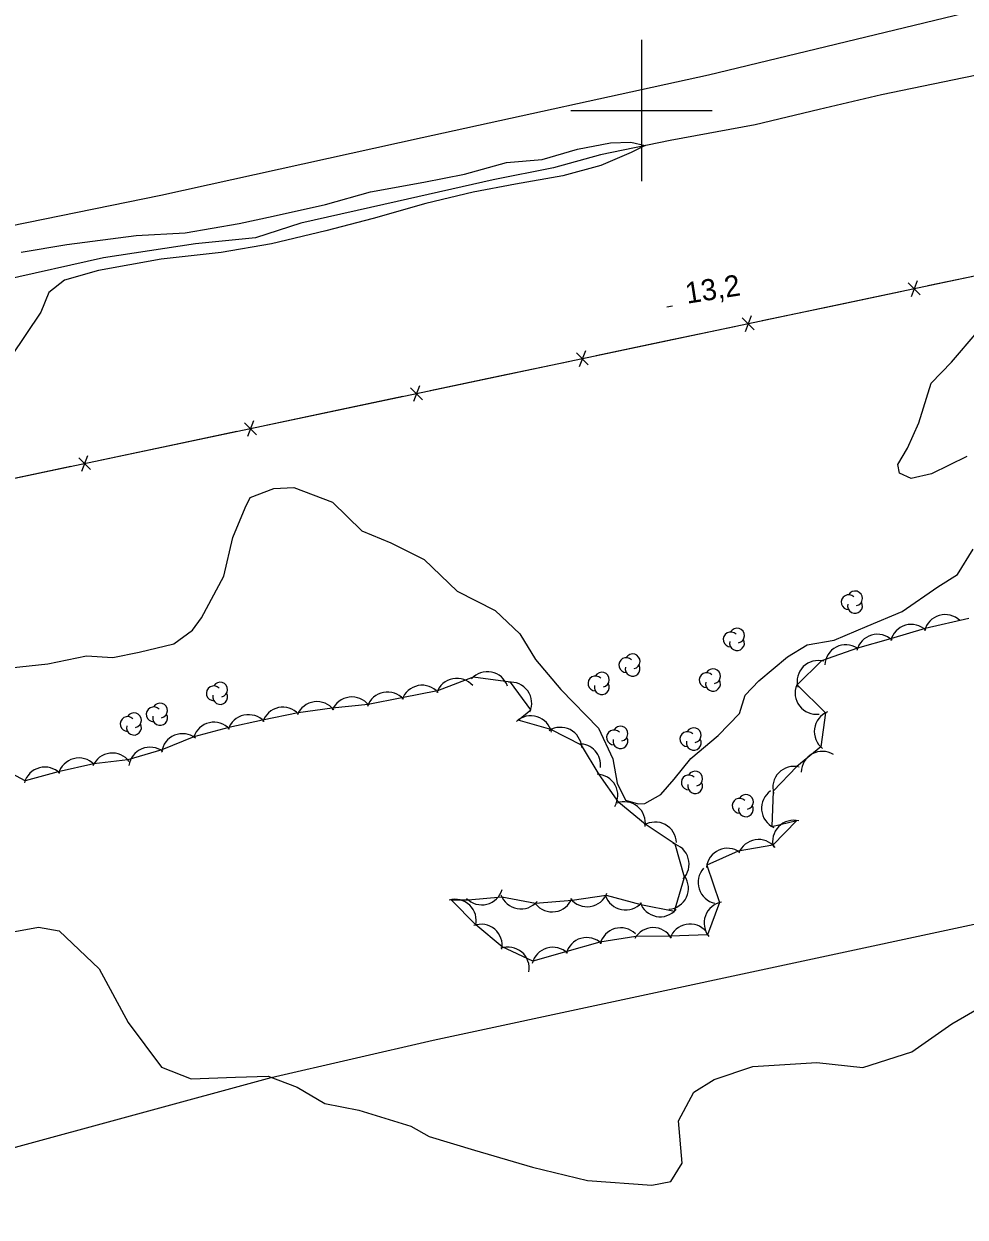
# Model space of a CAD drawing. Extents: x 643342 to 646936, y 5873857 to 5876103.
# Drawn here: x 645312.6 to 645445.8, y 5875443.4 to 5875612.3 of the extents above; entities that cross this region are included whole.
import ezdxf

# ---------------------------------------------------------------- set-up
doc = ezdxf.new("R2010")
doc.units = 0
for name, color, linetype in [('Niveau 1', 7, 'Continuous'), ('Niveau 2', 7, 'Continuous'), ('Niveau 25', 7, 'Continuous'), ('Niveau 3', 7, 'Continuous'), ('Niveau 37', 7, 'Continuous'), ('Niveau 4', 7, 'Continuous'), ('Niveau 44', 7, 'Continuous'), ('Niveau 61', 7, 'Continuous')]:
    doc.layers.add(name, color=color, linetype=linetype)

msp = doc.modelspace()

# ---------------------------------------------------------------- linework, layer by layer
at = {"layer": 'Niveau 1'}
for points in [[(645306.06, 5875482.87), (645314.63, 5875484.45), (645317.57, 5875483.95), (645323.22, 5875478.56), (645327.31, 5875470.98), (645332.05, 5875464.63), (645336.26, 5875462.97), (645342.5, 5875463.23), (645347.13, 5875463.36), (645351.27, 5875461.8), (645355.18, 5875459.52), (645359.97, 5875458.55), (645367.35, 5875456.3), (645369.92, 5875454.83), (645376.35, 5875452.9), (645384.56, 5875450.49)], [(645384.56, 5875450.49), (645392.37, 5875448.62), (645401.47, 5875447.92), (645404.14, 5875448.45), (645405.76, 5875451.05), (645405.23, 5875457.06), (645407.41, 5875461.11), (645410.26, 5875462.88), (645415.77, 5875464.72), (645424.81, 5875465.29), (645431.35, 5875464.6), (645438.27, 5875466.79), (645443.92, 5875470.79), (645452.23, 5875475.56)]]:
    msp.add_lwpolyline(points, dxfattribs=at)
at = {"layer": 'Niveau 2'}
for points in [[(645312.17, 5875579.97), (645318.62, 5875581.06), (645328.47, 5875582.33), (645335.38, 5875582.71), (645343.02, 5875584.02), (645347.84, 5875585.08), (645355.27, 5875586.72), (645361.65, 5875588.5), (645369.16, 5875589.86), (645374.96, 5875591.01), (645380.88, 5875592.64), (645385.93, 5875593.08), (645390.94, 5875594.56), (645395.6, 5875595.44), (645398.48, 5875595.52), (645400.53, 5875595.04), (645398.54, 5875594.05), (645394.26, 5875592.22), (645388.84, 5875590.76), (645382.18, 5875589.59), (645376.15, 5875588.48), (645369.48, 5875586.85), (645362.03, 5875584.74), (645355.3, 5875582.99), (645347.6, 5875581.15), (645340.47, 5875579.94), (645331.99, 5875578.96), (645323.11, 5875577.37), (645318.3, 5875576.01), (645316.09, 5875574.25), (645314.94, 5875571.46), (645310.7, 5875565.15)], [(645446.03, 5875551.06), (645441.06, 5875548.58), (645438.17, 5875547.92), (645436.54, 5875548.71), (645436.26, 5875549.9), (645437.67, 5875552.24), (645439.26, 5875555.81), (645441.01, 5875561.43), (645443.86, 5875564.41), (645447.52, 5875568.63)], [(645310.67, 5875521.15), (645315.95, 5875521.73), (645321.41, 5875522.86), (645325.14, 5875522.6), (645328.9, 5875523.35), (645333.77, 5875524.53), (645336.44, 5875526.46), (645337.73, 5875528.21), (645340.85, 5875534.13), (645342.16, 5875539.61), (645343.87, 5875543.78), (645344.61, 5875545.24), (645347.96, 5875546.53), (645350.79, 5875546.66), (645356.24, 5875544.58), (645360.42, 5875540.52), (645364.5, 5875538.85), (645369.22, 5875536.47), (645373.9, 5875531.99), (645379.29, 5875529.27), (645382.77, 5875525.96), (645385, 5875522.32), (645388.56, 5875518.09), (645393.9, 5875512.63), (645395.96, 5875508.27), (645396.56, 5875504.83), (645397.75, 5875502.43), (645399.54, 5875501.89), (645400.45, 5875501.97), (645402.71, 5875503.22), (645404.6, 5875505.37), (645407, 5875508.32)], [(645246.8, 5875436.74), (645309.81, 5875452.91), (645347.57, 5875463.16), (645370.52, 5875468.47), (645498.8, 5875495.97), (645554.04, 5875506.6), (645620.96, 5875521.54), (645671.93, 5875531.75), (645722.29, 5875544.6), (645729.55, 5875514.86), (645737.24, 5875468.76), (645738.05, 5875463.13)], [(645407, 5875508.32), (645410.87, 5875511.57), (645413.88, 5875514.69), (645414.69, 5875517.27), (645416.59, 5875519.3), (645420.68, 5875522.69), (645423.47, 5875524.39), (645427.28, 5875525.08), (645431.95, 5875527.06), (645436.9, 5875529.13), (645441.96, 5875532.61), (645444.75, 5875534.36), (645446.97, 5875537.94)]]:
    msp.add_lwpolyline(points, dxfattribs=at)
at = {"layer": 'Niveau 25'}
msp.add_lwpolyline([(645445.61, 5875613.76), (645409.5, 5875605.03), (645368.95, 5875596.13), (645331.96, 5875588), (645293.98, 5875580.24), (645259.57, 5875573.26), (645221.88, 5875566.21), (645187.82, 5875559.48), (645158.28, 5875553.85)], dxfattribs=at)
at = {"layer": 'Niveau 3'}
msp.add_line((645403.59, 5875572.25), (645404.38, 5875572.37), dxfattribs=at)
at = {"layer": 'Niveau 37'}
for points in [[(645661.64, 5875622.06), (645602.9, 5875609.55), (645529.72, 5875594.18), (645467.05, 5875580.77), (645368.14, 5875559.93), (645217.21, 5875528.14)], [(645450.34, 5875577.25), (645440.55, 5875575.19)], [(645439.43, 5875573.93), (645437.75, 5875575.62)], [(645439.02, 5875575.89), (645438.16, 5875573.66)], [(645436.64, 5875574.36), (645426.86, 5875572.3)], [(645426.86, 5875572.3), (645417.07, 5875570.24)], [(645413.16, 5875569.41), (645403.37, 5875567.35)], [(645413.16, 5875569.41), (645403.37, 5875567.35)], [(645415.95, 5875568.98), (645414.26, 5875570.67)], [(645415.53, 5875570.94), (645414.67, 5875568.71)], [(645392.05, 5875565.99), (645391.19, 5875563.76)], [(645403.37, 5875567.35), (645393.59, 5875565.29)], [(645389.67, 5875564.47), (645379.89, 5875562.4)], [(645392.46, 5875564.03), (645390.78, 5875565.72)], [(645368.56, 5875561.04), (645367.7, 5875558.82)], [(645379.89, 5875562.4), (645370.1, 5875560.34)], [(645366.19, 5875559.52), (645356.4, 5875557.46)], [(645368.98, 5875559.08), (645367.29, 5875560.77)], [(645345.49, 5875554.14), (645343.81, 5875555.83)], [(645345.08, 5875556.09), (645344.22, 5875553.87)], [(645356.4, 5875557.46), (645346.62, 5875555.4)], [(645342.7, 5875554.57), (645332.92, 5875552.51)], [(645332.92, 5875552.51), (645323.13, 5875550.45)], [(645322.01, 5875549.19), (645320.32, 5875550.88)], [(645321.59, 5875551.15), (645320.74, 5875548.92)], [(645319.22, 5875549.63), (645309.43, 5875547.56)]]:
    msp.add_lwpolyline(points, dxfattribs=at)
at = {"layer": 'Niveau 4'}
msp.add_lwpolyline([(645457.63, 5875607.09), (645445.62, 5875604.64), (645433.96, 5875602.22), (645425.14, 5875600.17), (645416.1, 5875597.99), (645404.05, 5875595.77), (645394.18, 5875593.74), (645387.53, 5875591.88), (645379.01, 5875590.2), (645365.4, 5875587.14), (645351.79, 5875584.08), (645345.37, 5875582.01), (645336.88, 5875581.14), (645323.85, 5875579.18), (645309.53, 5875575.95)], dxfattribs=at)
at = {"layer": 'Niveau 44'}
for points in [[(645446.35, 5875528.14), (645440.17, 5875526.7), (645435.23, 5875525.27), (645430.57, 5875523.91), (645425.5, 5875522.14), (645422.04, 5875518.73), (645426.04, 5875514.76), (645425.38, 5875509.95), (645422, 5875507.17), (645418.62, 5875503.68), (645418.44, 5875498.7), (645421.98, 5875499.55), (645418.61, 5875496.06), (645413.67, 5875495.21), (645409.24, 5875493.23), (645411.03, 5875487.93), (645409.35, 5875483.37), (645404.06, 5875483.17), (645399.2, 5875483.11), (645394.09, 5875482.34)], [(645394.09, 5875482.34), (645389.43, 5875481), (645384.62, 5875479.62), (645380.27, 5875481.65), (645376.56, 5875484.77), (645373.07, 5875488.34), (645375.46, 5875488.31), (645380.22, 5875488.73), (645385, 5875487.85), (645390.17, 5875488.25), (645394.97, 5875488.96), (645399.92, 5875487.66), (645404.68, 5875486.71), (645406.08, 5875491.51), (645404.77, 5875496.18), (645400.53, 5875499.03), (645396.78, 5875502.11), (645394.02, 5875506.06), (645391.49, 5875510.19), (645387.17, 5875512.41), (645382.54, 5875513.76), (645384.31, 5875515.2), (645381.47, 5875519.13), (645376.15, 5875519.83), (645371.13, 5875517.91), (645366.08, 5875516.92), (645361.32, 5875515.98), (645356.22, 5875515.43), (645351.41, 5875514.78), (645346.34, 5875513.76), (645341.6, 5875512.72), (645336.6, 5875511.39), (645332.11, 5875509.53), (645327.29, 5875508.12), (645322.47, 5875507.56), (645317.42, 5875506.43), (645312.73, 5875505.18), (645308.49, 5875507.4)]]:
    msp.add_lwpolyline(points, dxfattribs=at)
for centre, radius, start, end in [((645429.32, 5875530.44), 1.05, 44.1154, 269.804), ((645430.22, 5875530.97), 1.05, 282.2692, 149.7263), ((645430.22, 5875529.92), 1.05, 166.9369, 29.6212), ((645438.19, 5875524.29), 3, 46.2192, 166.1972), ((645438.19, 5875524.29), 3, 46.2192, 166.1972), ((645438.19, 5875524.29), 3, 46.2192, 166.1972), ((645442.99, 5875525.68), 3, 46.2192, 166.1972), ((645442.99, 5875525.68), 3, 46.2192, 166.1972), ((645442.99, 5875525.68), 3, 46.2192, 166.1972), ((645412.62, 5875525.17), 1.05, 44.1154, 269.804), ((645413.52, 5875525.7), 1.05, 282.2692, 149.7263), ((645433.39, 5875522.89), 3, 46.2192, 166.1972), ((645433.39, 5875522.89), 3, 46.2192, 166.1972), ((645433.39, 5875522.89), 3, 46.2192, 166.1972), ((645413.52, 5875524.65), 1.05, 166.9369, 29.6212), ((645428.93, 5875521.42), 3, 57.2871, 177.265), ((645428.93, 5875521.42), 3, 57.2871, 177.265), ((645428.93, 5875521.42), 3, 57.2871, 177.265), ((645397.84, 5875521.53), 1.05, 44.1154, 269.804), ((645398.74, 5875522.06), 1.05, 282.2692, 149.7263), ((645425.01, 5875519.18), 3, 74.6096, 194.5876), ((645425.01, 5875519.18), 3, 74.6096, 194.5876), ((645425.01, 5875519.18), 3, 74.6096, 194.5876), ((645378.17, 5875517.61), 3, 18.4791, 138.4571), ((645378.17, 5875517.61), 3, 18.4791, 138.4571), ((645378.17, 5875517.61), 3, 18.4791, 138.4571), ((645394.37, 5875519.47), 1.05, 282.2692, 149.7263), ((645398.74, 5875521.01), 1.05, 166.9369, 29.6212), ((645409.22, 5875519.42), 1.05, 44.1154, 269.804), ((645410.12, 5875519.95), 1.05, 282.2692, 149.7263), ((645340.35, 5875518.07), 1.05, 282.2692, 149.7263), ((645368.95, 5875515.68), 3, 41.1426, 161.1206), ((645368.95, 5875515.68), 3, 41.1426, 161.1206), ((645368.95, 5875515.68), 3, 41.1426, 161.1206), ((645373.86, 5875516.65), 3, 41.1426, 161.1206), ((645373.86, 5875516.65), 3, 41.1426, 161.1206), ((645373.86, 5875516.65), 3, 41.1426, 161.1206), ((645381.46, 5875516.13), 3, 335.894, 95.8719), ((645381.46, 5875516.13), 3, 335.894, 95.8719), ((645381.46, 5875516.13), 3, 335.894, 95.8719), ((645393.47, 5875518.94), 1.05, 44.1154, 269.804), ((645394.37, 5875518.42), 1.05, 166.9369, 29.6212), ((645410.12, 5875518.9), 1.05, 166.9369, 29.6212), ((645424.74, 5875517.58), 3, 157.6995, 277.6775), ((645424.74, 5875517.58), 3, 157.6995, 277.6775), ((645424.74, 5875517.58), 3, 157.6995, 277.6775), ((645339.45, 5875517.54), 1.05, 44.1154, 269.804), ((645340.35, 5875517.02), 1.05, 166.9369, 29.6212), ((645359, 5875514.02), 3, 37.6436, 157.6215), ((645359, 5875514.02), 3, 37.6436, 157.6215), ((645359, 5875514.02), 3, 37.6436, 157.6215), ((645364.04, 5875514.72), 3, 41.1426, 161.1206), ((645364.04, 5875514.72), 3, 41.1426, 161.1206), ((645364.04, 5875514.72), 3, 41.1426, 161.1206), ((645330.94, 5875514.57), 1.05, 44.1154, 269.804), ((645331.84, 5875515.1), 1.05, 282.2692, 149.7263), ((645349.23, 5875512.58), 3, 42.3292, 162.3071), ((645349.23, 5875512.58), 3, 42.3292, 162.3071), ((645349.23, 5875512.58), 3, 42.3292, 162.3071), ((645354.05, 5875513.36), 3, 37.6436, 157.6215), ((645354.05, 5875513.36), 3, 37.6436, 157.6215), ((645354.05, 5875513.36), 3, 37.6436, 157.6215), ((645327.25, 5875513.2), 1.05, 44.1154, 269.804), ((645328.15, 5875513.73), 1.05, 282.2692, 149.7263), ((645331.84, 5875514.05), 1.05, 166.9369, 29.6212), ((645344.35, 5875511.52), 3, 42.3292, 162.3071), ((645344.35, 5875511.52), 3, 42.3292, 162.3071), ((645344.35, 5875511.52), 3, 42.3292, 162.3071), ((645384.33, 5875511.36), 3, 12.7906, 132.7685), ((645384.33, 5875511.36), 3, 12.7906, 132.7685), ((645384.33, 5875511.36), 3, 12.7906, 132.7685), ((645427.46, 5875512.12), 3, 112.2209, 232.1989), ((645427.46, 5875512.12), 3, 112.2209, 232.1989), ((645427.46, 5875512.12), 3, 112.2209, 232.1989), ((645328.15, 5875512.68), 1.05, 166.9369, 29.6212), ((645339.46, 5875510.45), 3, 42.3292, 162.3071), ((645339.46, 5875510.45), 3, 42.3292, 162.3071), ((645339.46, 5875510.45), 3, 42.3292, 162.3071), ((645388.53, 5875509.73), 3, 2.7752, 122.7532), ((645388.53, 5875509.73), 3, 2.7752, 122.7532), ((645388.53, 5875509.73), 3, 2.7752, 122.7532), ((645396.11, 5875511.3), 1.05, 44.1154, 269.804), ((645397.01, 5875511.83), 1.05, 282.2692, 149.7263), ((645406.49, 5875511.07), 1.05, 44.1154, 269.804), ((645407.39, 5875511.6), 1.05, 282.2692, 149.7263), ((645335.03, 5875508.83), 3, 52.5092, 172.4872), ((645335.03, 5875508.83), 3, 52.5092, 172.4872), ((645335.03, 5875508.83), 3, 52.5092, 172.4872), ((645391.2, 5875507.38), 3, 353.3344, 91.0229), ((645391.2, 5875507.38), 3, 353.3344, 91.0229), ((645391.2, 5875507.38), 3, 353.3344, 91.0229), ((645397.01, 5875510.78), 1.05, 166.9369, 29.6212), ((645407.39, 5875510.55), 1.05, 166.9369, 29.6212), ((645325.08, 5875506.09), 3, 36.7007, 156.6786), ((645325.08, 5875506.09), 3, 36.7007, 156.6786), ((645325.08, 5875506.09), 3, 36.7007, 156.6786), ((645330.41, 5875506.92), 3, 52.5092, 172.4872), ((645330.41, 5875506.92), 3, 52.5092, 172.4872), ((645330.41, 5875506.92), 3, 52.5092, 172.4872), ((645425.6, 5875506.33), 3, 58.6236, 178.6016), ((645425.6, 5875506.33), 3, 58.6236, 178.6016), ((645425.6, 5875506.33), 3, 58.6236, 178.6016), ((645315.53, 5875504.1), 3, 44.909, 164.8869), ((645315.53, 5875504.1), 3, 44.909, 164.8869), ((645315.53, 5875504.1), 3, 44.909, 164.8869), ((645320.36, 5875505.39), 3, 44.909, 164.8869), ((645320.36, 5875505.39), 3, 44.909, 164.8869), ((645320.36, 5875505.39), 3, 44.909, 164.8869), ((645421.58, 5875504.2), 3, 75.9296, 195.9075), ((645421.58, 5875504.2), 3, 75.9296, 195.9075), ((645421.58, 5875504.2), 3, 75.9296, 195.9075), ((645393.64, 5875503.09), 3, 328.7665, 88.7445), ((645393.64, 5875503.09), 3, 328.7665, 88.7445), ((645393.64, 5875503.09), 3, 328.7665, 88.7445), ((645406.69, 5875504.94), 1.05, 44.1154, 269.804), ((645407.59, 5875505.47), 1.05, 282.2692, 149.7263), ((645407.59, 5875504.42), 1.05, 166.9369, 29.6212), ((645419.98, 5875501.27), 3, 125.1188, 245.0967), ((645419.98, 5875501.27), 3, 125.1188, 245.0967), ((645419.98, 5875501.27), 3, 125.1188, 245.0967), ((645397.54, 5875499.2), 3, 350.6663, 110.6443), ((645397.54, 5875499.2), 3, 350.6663, 110.6443), ((645397.54, 5875499.2), 3, 350.6663, 110.6443), ((645413.88, 5875501.64), 1.05, 44.1154, 269.804), ((645414.78, 5875502.17), 1.05, 282.2692, 149.7263), ((645414.78, 5875501.12), 1.05, 166.9369, 29.6212), ((645401.95, 5875496.32), 3, 2.0141, 121.9921), ((645401.95, 5875496.32), 3, 2.0141, 121.9921), ((645401.95, 5875496.32), 3, 2.0141, 121.9921), ((645421.56, 5875496.58), 3, 75.9334, 195.9114), ((645421.56, 5875496.58), 3, 75.9334, 195.9114), ((645421.56, 5875496.58), 3, 75.9334, 195.9114), ((645416.57, 5875493.85), 3, 39.0443, 159.0222), ((645416.57, 5875493.85), 3, 39.0443, 159.0222), ((645416.57, 5875493.85), 3, 39.0443, 159.0222), ((645403.73, 5875493.37), 3, 315.6596, 75.6376), ((645403.73, 5875493.37), 3, 315.6596, 75.6376), ((645403.73, 5875493.37), 3, 315.6596, 75.6376), ((645412.17, 5875492.61), 3, 54.1725, 174.1505), ((645412.17, 5875492.61), 3, 54.1725, 174.1505), ((645412.17, 5875492.61), 3, 54.1725, 174.1505), ((645403.64, 5875489.97), 3, 274.5841, 34.5621), ((645403.64, 5875489.97), 3, 274.5841, 34.5621), ((645403.64, 5875489.97), 3, 274.5841, 34.5621), ((645411, 5875490.77), 3, 137.8292, 257.8071), ((645411, 5875490.77), 3, 137.8292, 257.8071), ((645411, 5875490.77), 3, 137.8292, 257.8071), ((645373.59, 5875485.39), 3, 346.1029, 106.0808), ((645373.59, 5875485.39), 3, 346.1029, 106.0808), ((645373.59, 5875485.39), 3, 346.1029, 106.0808), ((645377.39, 5875490.61), 3, 224.0586, 344.0366), ((645377.39, 5875490.61), 3, 224.0586, 344.0366), ((645377.39, 5875490.61), 3, 224.0586, 344.0366), ((645382.93, 5875490.03), 3, 199.5334, 319.5113), ((645382.93, 5875490.03), 3, 199.5334, 319.5113), ((645382.93, 5875490.03), 3, 199.5334, 319.5113), ((645387.36, 5875489.62), 3, 218.412, 338.3899), ((645387.36, 5875489.62), 3, 218.412, 338.3899), ((645387.36, 5875489.62), 3, 218.412, 338.3899), ((645392.31, 5875490.35), 3, 218.412, 338.3899), ((645392.31, 5875490.35), 3, 218.412, 338.3899), ((645392.31, 5875490.35), 3, 218.412, 338.3899), ((645397.74, 5875489.89), 3, 198.773, 318.7509), ((645397.74, 5875489.89), 3, 198.773, 318.7509), ((645397.74, 5875489.89), 3, 198.773, 318.7509), ((645402.64, 5875488.92), 3, 198.773, 318.7509), ((645402.64, 5875488.92), 3, 198.773, 318.7509), ((645402.64, 5875488.92), 3, 198.773, 318.7509), ((645411.85, 5875485.04), 3, 99.8218, 219.7997), ((645411.85, 5875485.04), 3, 99.8218, 219.7997), ((645411.85, 5875485.04), 3, 99.8218, 219.7997), ((645406.87, 5875481.89), 3, 40.8764, 160.8544), ((645406.87, 5875481.89), 3, 40.8764, 160.8544), ((645406.87, 5875481.89), 3, 40.8764, 160.8544), ((645377.28, 5875481.86), 3, 349.9156, 109.8936), ((645377.28, 5875481.86), 3, 349.9156, 109.8936), ((645377.28, 5875481.86), 3, 349.9156, 109.8936), ((645397.05, 5875481.36), 3, 46.0409, 166.0188), ((645397.05, 5875481.36), 3, 46.0409, 166.0188), ((645397.05, 5875481.36), 3, 46.0409, 166.0188), ((645401.65, 5875481.38), 3, 30.6922, 150.6701), ((645401.65, 5875481.38), 3, 30.6922, 150.6701), ((645401.65, 5875481.38), 3, 30.6922, 150.6701), ((645381.1, 5875478.64), 3, 349.9156, 109.8936), ((645381.1, 5875478.64), 3, 349.9156, 109.8936), ((645381.1, 5875478.64), 3, 349.9156, 109.8936), ((645387.44, 5875478.6), 3, 46.0409, 166.0188), ((645387.44, 5875478.6), 3, 46.0409, 166.0188), ((645387.44, 5875478.6), 3, 46.0409, 166.0188), ((645392.25, 5875479.98), 3, 46.0409, 166.0188), ((645392.25, 5875479.98), 3, 46.0409, 166.0188), ((645392.25, 5875479.98), 3, 46.0409, 166.0188)]:
    msp.add_arc(centre, radius, start, end, dxfattribs=at)
at = {"layer": 'Niveau 61'}
for points in [[(645400, 5875610), (645400, 5875600), (645400, 5875590)], [(645390, 5875600), (645400, 5875600), (645410, 5875600)]]:
    msp.add_lwpolyline(points, dxfattribs=at)

# ---------------------------------------------------------------- texts
at = {"layer": 'Niveau 3'}
msp.add_text('13,2 ', height=3, rotation=8.941, dxfattribs=at).set_placement((645406.44, 5875572.66))

doc.saveas('drawing.dxf')
